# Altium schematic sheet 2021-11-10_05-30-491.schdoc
size 372 x 134 mm; SheetNumber: 1; SheetTotal: 1
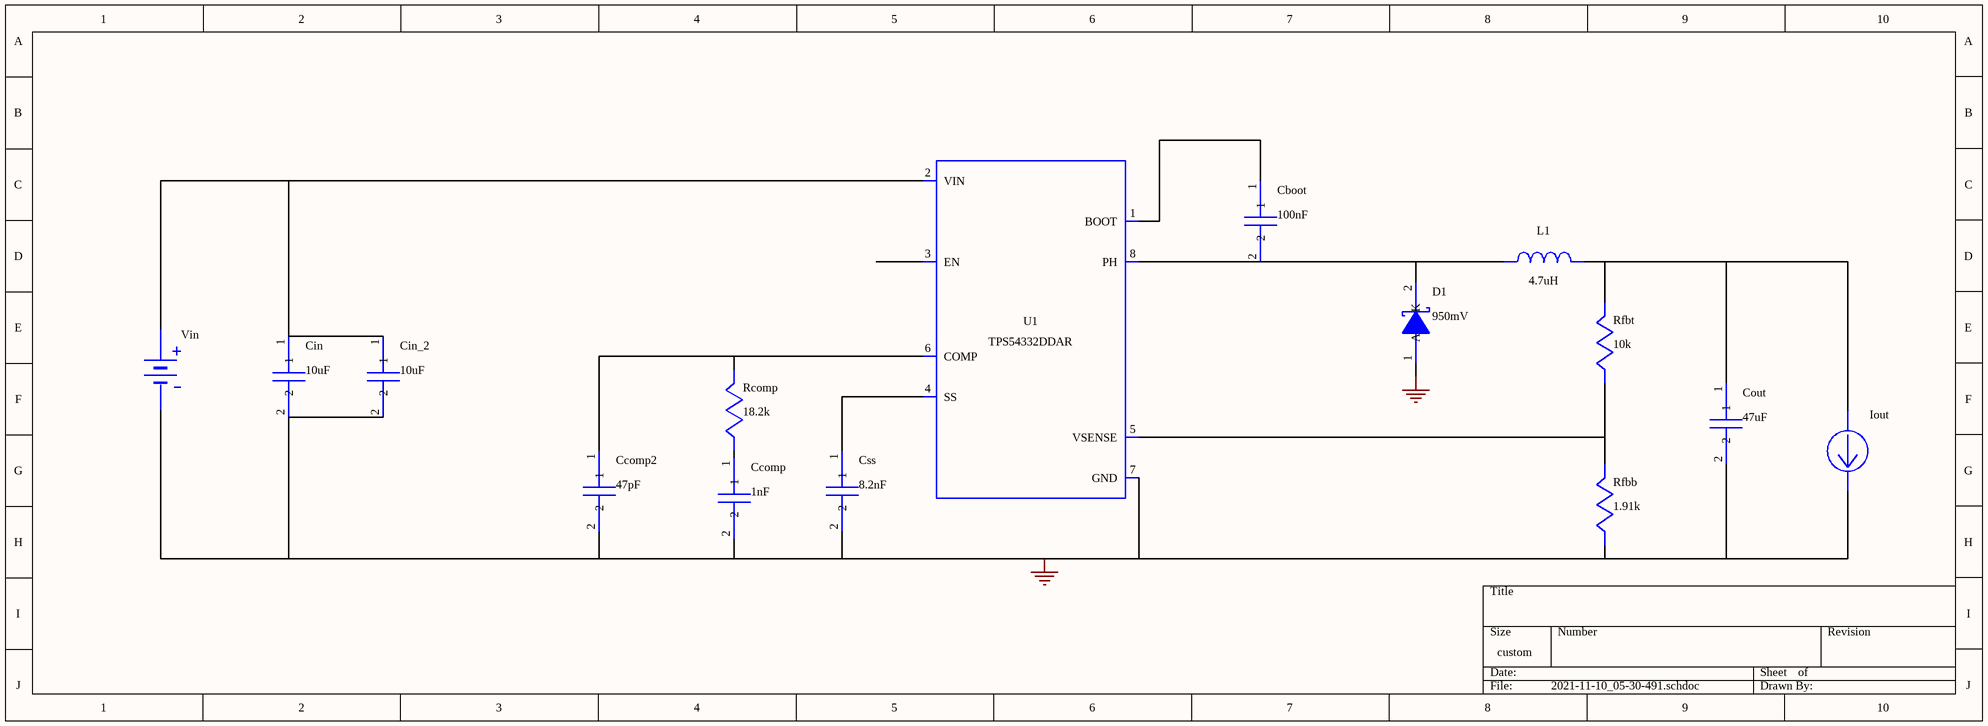
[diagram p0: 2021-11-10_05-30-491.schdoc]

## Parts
Cboot  value 100nF  (hidden comment: GRM155R71A104KA01D)
Ccomp  value 1nF  (hidden comment: GRM1555C1H102JA01J)
Ccomp2  value 47pF  (hidden comment: CL21C470JBANNNC)
Cin  value 10uF  (hidden comment: C3225X7R1H106M250AC)
Cin_2  value 10uF  (hidden comment: C3225X7R1H106M250AC)
Cout  value 47uF  (hidden comment: C4532X5R1A476M280KA)
Css  value 8.2nF  (hidden comment: GRM033R71A822KA01D)
D1  value 950mV  (hidden comment: SBRD10200TR)
Iout  WB_CURRENT_LOAD  (value not drawn)
L1  value 4.7uH  (hidden comment: SDR1005-4R7ML)
Rcomp  value 18.2k  (hidden comment: CRCW040218K2FKED)
Rfbb  value 1.91k  (hidden comment: CRCW04021K91FKED)
Rfbt  value 10k  (hidden comment: RC0201FR-0710KL)
U1  TPS54332DDAR
Vin  WB_BATTERY  (value not drawn)

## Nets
0: Ccomp.2 Ccomp2.2 Cin.2 Cin_2.2 Cout.2 Css.2 D1.1(A) D1.3(A) Iout.2(-) Rfbb.2 U1.7(GND) U1.9(ETPAD) Vin.2(-)
NetCboot_1: Cboot.1 U1.1(BOOT)
NetCboot_2: Cboot.2 D1.2(K) L1.2 U1.8(PH)
NetCcomp2_1: Ccomp2.1 Rcomp.1 U1.6(COMP)
NetCcomp_1: Ccomp.1 Rcomp.2
NetCin_1: Cin.1 Cin_2.1 U1.2(VIN) Vin.1(+)
NetCout_1: Cout.1 Iout.1(+) L1.1 Rfbt.1
NetCss_1: Css.1 U1.4(SS)
NetRfbb_1: Rfbb.1 Rfbt.2 U1.5(VSENSE)

Not connected (* = marked no-connect by the designer): U1 3(EN)

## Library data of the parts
Cboot = GRM155R71A104KA01D: GRM155R71A104KA0; Manufacturer Name: MuRata
Ccomp = GRM1555C1H102JA01J: GRM1555C1H102JA0; Manufacturer Name: MuRata
Ccomp2 = CL21C470JBANNNC: Manufacturer Name: Samsung Electro-Mechanics
Cin Cin_2 = C3225X7R1H106M250AC: C3225X7R1H106M25; Manufacturer Name: TDK
Cout = C4532X5R1A476M280KA: C4532X5R1A476M28; Manufacturer Name: TDK
Css = GRM033R71A822KA01D: GRM033R71A822KA0; Manufacturer Name: MuRata
D1 = SBRD10200TR: Manufacturer Name: SMC Diode Solutions
L1 = SDR1005-4R7ML: Manufacturer Name: Bourns
Rcomp = CRCW040218K2FKED: Manufacturer Name: Vishay-Dale
Rfbb = CRCW04021K91FKED: Manufacturer Name: Vishay-Dale
Rfbt = RC0201FR-0710KL: Manufacturer Name: Yageo
U1 = TPS54332DDAR: Manufacturer Name: Texas Instruments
